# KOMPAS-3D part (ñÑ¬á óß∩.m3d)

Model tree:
1. Эскиз:1
2. Операция выдавливания:1
     Расстояние 1 = 0.6
3. Эскиз:2
4. Вырезать элемент выдавливания:1
     Толщина стенки 1 = 3; Толщина стенки 2 = 3; Расстояние 1 = 10
5. Эскиз:3
6. Вырезать элемент выдавливания:2
     Толщина стенки 1 = 3; Толщина стенки 2 = 3; Расстояние 1 = 10
7. Эскиз:4
8. Вырезать элемент выдавливания:3
     Толщина стенки 1 = 3; Толщина стенки 2 = 3; Расстояние 1 = 10
